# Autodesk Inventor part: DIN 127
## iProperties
Company: Bakker Hydraulic B.V.
Shininess: 64.0
Length Units: 11269
Angle Units: 11279
Time Units: 11290
Mass Units: 11283
Length Display Precision: 3
Angle Display Precision: 2
Compacted: True
Part Number: DIN 127
Document SubType Name: Modeling
Created: 2002-12
Designer: Cor de Vlaming
Engineer: Cor de Vlaming
Material: Verenstaal
Description: DIN 127 - M18
Density: 0.0
Volumn: 0.0
Area: 0.0
PropertySet Name: Model Information
Control State: 0
Master: False
Checked Out: False
Author: Cor de Vlaming
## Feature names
1. Revolution1
2. Extrusion1
